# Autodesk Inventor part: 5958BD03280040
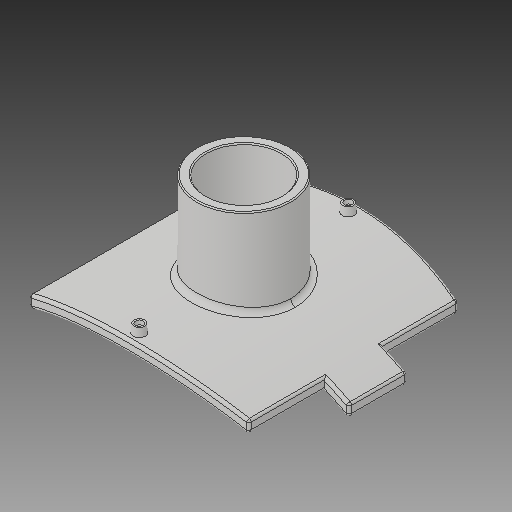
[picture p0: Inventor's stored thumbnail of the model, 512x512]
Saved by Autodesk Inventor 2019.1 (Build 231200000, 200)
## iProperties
Created: 2017-10
Part Number: 5958BD03280040
Material: Generic
Description: PLASSON BRANCH SADDLE 18''-28''IPS x 16''-24''DIPS
Document SubType Name: Modeling
Designer: KIM
Density: 1 g/cm^3
Appearance: Default
Author: KIM
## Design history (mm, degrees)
derived "5958B-1.ipt"
feature "Solid1::5958B-1.ipt"
tag "TaggingFeature1"
body "Solid1"
other parameters: "d0" = 708, "d1" = 14.986, "d2" = 283.464, "d3" = 299.974, "d4" = 0, "d5" = 314.96, "d6" = 74.9935, "d7" = 0, "d8" = 134.9883, "d10" = 0, "d11" = 3.54, "d12" = 379.6, "d13" = 14, "d14" = 134.9883, "d16" = 5 deg, "d18" = 4, "d19" = 14, "d20" = 0, "d21" = 3, "d22" = 0, "d23" = 478.968, "d24" = 121.3, "d25" = 16, "d26" = 97.04, "d28" = 0, "d29" = 9.6, "d31" = 0, "d32" = 87.4776, "d33" = 0, "d34" = 7.08, "d35" = 1.416, "d_" = 708, "d_1" = 121.3, "B_" = 314.96, "H_" = 124.968, "L_" = 299.974, "x_" = 14.986, "D_" = 16, "H1" = 109.982
